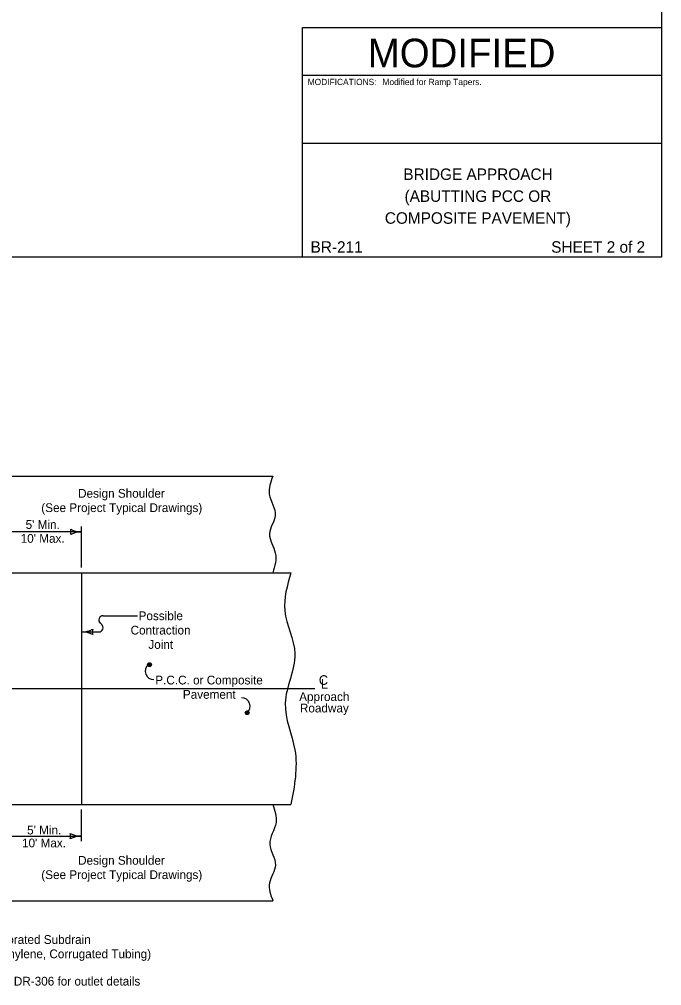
# Model space of a CAD drawing. Extents: x 10045 to 81668, y 6370 to 11018.
# Drawn here: x 22837 to 24068, y 6527 to 8380 of the extents above; entities that cross this region are included whole.
import ezdxf

# ---------------------------------------------------------------- set-up
doc = ezdxf.new("R2010")
doc.units = 0
for name, color, linetype in [('Alignment', 7, 'Continuous'), ('Bridge', 7, 'Continuous'), ('dsnStdLineWork', 7, 'Continuous'), ('Level 5', 7, 'Continuous')]:
    doc.layers.add(name, color=color, linetype=linetype)

msp = doc.modelspace()

# ---------------------------------------------------------------- linework, layer by layer
at = {"layer": 'Alignment'}
for p, q in [((22956.4, 7397.2), (22811.9, 7397.2)), ((22956.4, 7329), (22956.4, 7407.4)), ((22997.7, 7236.4), (23063.3, 7236.4)), ((22993.6, 7220.9), (22992.3, 7222)), ((22956.7, 7205.3), (22989.4, 7205.3)), ((23182, 7096.7), (23182, 7096.7)), ((22955.5, 6865), (22955.5, 6804.1)), ((22811.9, 6813.7), (22955.5, 6813.7))]:
    msp.add_line(p, q, dxfattribs=at)
for centre, radius, start, end in [((22997.7, 7228.2), 8.22, 90, 228.6908), ((22989.4, 7213.6), 8.22, 270, 48.691), ((23094.6, 7130.2), 16.4, 131.3092, 270), ((23262.7, 7062.7), 16.4, 311.309, 90)]:
    msp.add_arc(centre, radius, start, end, dxfattribs=at)
at = {"layer": 'Bridge'}
for p, q in [((23379.5, 8272.7), (24067.5, 8272.7)), ((23379.5, 8142.2), (24067.5, 8142.2))]:
    msp.add_line(p, q, dxfattribs=at)
msp.add_lwpolyline([(23379.5, 8364), (24067.5, 8364), (24067.5, 7924), (23379.5, 7924)], close=True, dxfattribs=at)
at = {"layer": 'dsnStdLineWork'}
for p, q in [((22811.9, 7503.7), (23322.7, 7503.7)), ((22811.9, 7318.7), (23357.5, 7318.7)), ((22956.4, 7318.7), (22956.4, 6874.6)), ((22994.9, 7219.7), (22993.6, 7220.9)), ((21886.8, 7096.7), (23403.1, 7096.7)), ((22811.9, 6874.6), (23357.5, 6874.6)), ((22811.9, 6689.6), (23322.7, 6689.6))]:
    msp.add_line(p, q, dxfattribs=at)
for points in [[(23086.3, 7139.3), (23087.5, 7139.8), (23089.4, 7140.4), (23089.7, 7142.3), (23089.5, 7144), (23088.3, 7145.6), (23086.5, 7145.4), (23084.6, 7145.2), (23083.6, 7143.6), (23083.5, 7142), (23084.6, 7140), (23086, 7139.8), (23087.9, 7140.3), (23089.4, 7141.5), (23089.4, 7143.3), (23088.2, 7144.7), (23086.5, 7144.9), (23084.6, 7144.5), (23084.3, 7143.5), (23083.9, 7142.2), (23084.8, 7140.6), (23086.2, 7140.7), (23087.7, 7140.9), (23088.9, 7141.8), (23088.3, 7143.4), (23087.1, 7144.3), (23085.5, 7144.3), (23085.1, 7143.5), (23084.6, 7142.5), (23085.4, 7141.3), (23086.6, 7141), (23087.6, 7141.5), (23087.7, 7142.7), (23087.1, 7143.5), (23086.1, 7143.8), (23085.6, 7143.4), (23085.3, 7142.7), (23085.8, 7141.8), (23086.6, 7141.6), (23087.3, 7142.1), (23087.2, 7142.7), (23086.6, 7143.1), (23085.9, 7143.1), (23085.9, 7142.5), (23086.5, 7142.2)], [(23273.3, 7047), (23274.5, 7047.6), (23276.4, 7048.2), (23276.8, 7050.1), (23276.5, 7051.8), (23275.3, 7053.3), (23273.5, 7053.2), (23271.6, 7052.9), (23270.7, 7051.4), (23270.5, 7049.8), (23271.7, 7047.7), (23273, 7047.5), (23274.9, 7048), (23276.5, 7049.2), (23276.4, 7051), (23275.2, 7052.5), (23273.5, 7052.6), (23271.6, 7052.3), (23271.3, 7051.2), (23271, 7049.9), (23271.8, 7048.3), (23273.2, 7048.4), (23274.8, 7048.6), (23275.9, 7049.5), (23275.4, 7051.1), (23274.2, 7052), (23272.6, 7052.1), (23272.2, 7051.2), (23271.7, 7050.2), (23272.5, 7049), (23273.6, 7048.7), (23274.7, 7049.3), (23274.8, 7050.4), (23274.2, 7051.3), (23273.1, 7051.6), (23272.6, 7051.1), (23272.3, 7050.5), (23272.9, 7049.5), (23273.6, 7049.4), (23274.3, 7049.8), (23274.2, 7050.4), (23273.7, 7050.8), (23272.9, 7050.8), (23273, 7050.3), (23273.6, 7050)]]:
    msp.add_lwpolyline(points, dxfattribs=at)
for centre in [(23086.5, 7142.6), (23273.6, 7050.3)]:
    msp.add_circle(centre, 3.6, dxfattribs=at)
for centre, radius, start, end in [((22919.2, 7397.2), 17.1, 342.2666, 17.7334), ((22956.4, 7441.5), 44.4, 241.9275, 270), ((22956.4, 7352.8), 44.4, 90, 118.0725), ((22956.6, 7249.7), 44.4, 270, 298.0725), ((22993.9, 7205.3), 17.1, 162.2666, 197.7334), ((22956.6, 7161), 44.4, 61.9275, 90), ((22918.1, 6813.7), 17.2, 342.2666, 17.7334), ((22955.5, 6858.3), 44.6, 241.9275, 270), ((22955.5, 6769.1), 44.6, 90, 118.0725)]:
    msp.add_arc(centre, radius, start, end, dxfattribs=at)
for points in [[(23322.7, 7503.7), (23315.8, 7469.5), (23327.5, 7428.8), (23316.2, 7393.3), (23327.5, 7356.7), (23322.7, 7318.7)], [(23357.5, 7318.7), (23345.6, 7246), (23364.9, 7163.4), (23346.4, 7068.5), (23364.9, 6979), (23357.5, 6874.6)], [(23322.7, 6874.6), (23328.8, 6839.9), (23316.7, 6798.1), (23327.8, 6758.3), (23316.4, 6723.9), (23322.7, 6689.6)]]:
    msp.add_spline(points, degree=3, dxfattribs=at)
at = {"layer": 'Level 5'}
msp.add_lwpolyline([(20932.5, 9944), (24067.5, 9944), (24067.5, 7924), (20932.5, 7924)], close=True, dxfattribs=at)

# ---------------------------------------------------------------- texts
at = {"layer": 'Alignment'}
for s, height, p in [('Design Shoulder', 16.8, (22949.7, 7462.6)), ('(See Project Typical Drawings)', 16.8, (22879.2, 7435.1)), ("5' Min.", 16.8, (22849.2, 7402.8)), ("10' Max.", 16.8, (22839.7, 7376.2)), ('Possible', 16.8, (23065.6, 7227.8)), ('Contraction', 16.8, (23050.3, 7200.3)), ('Joint', 16.8, (23084.3, 7172.8)), ('P.C.C. or Composite', 16.8, (23097.5, 7104.6)), ('C', 18.4, (23410.8, 7103.8)), ('L', 18.4, (23414.6, 7096.6)), ('Pavement', 16.8, (23150.4, 7077.1)), ('Approach', 16.8, (23373.2, 7072.8)), ('Roadway', 16.8, (23374.6, 7050.9)), ("5' Min.", 16.8, (22852, 6817)), ("10' Max.", 16.8, (22842.3, 6792.2)), ('Design Shoulder', 16.8, (22949.7, 6758.9)), ('(See Project Typical Drawings)', 16.8, (22879.2, 6731.4)), ('4" Perforated Subdrain ', 16.8, (22746.1, 6607.1)), ('(Polyethylene, Corrugated Tubing)', 16.8, (22746.1, 6579.6)), ('See DR-306 for outlet details', 16.8, (22780.4, 6527.2))]:
    msp.add_text(s, height=height, dxfattribs=at).set_placement(p)
at = {"layer": 'Bridge'}
for s, height, p in [('MODIFIED', 55, (23504.6, 8287.8)), ('MODIFICATIONS:', 12, (23389.5, 8253.8)), ('Modified for Ramp Tapers.', 12, (23532.7, 8253.8)), ('BRIDGE APPROACH', 22, (23572.7, 8071.9)), ('(ABUTTING PCC OR', 22, (23575, 8029.9)), ('COMPOSITE PAVEMENT)', 22, (23537.3, 7987.9)), ('BR-211', 22, (23395, 7932.4)), ('SHEET 2 of 2', 22, (23856, 7932.4))]:
    msp.add_text(s, height=height, dxfattribs=at).set_placement(p)

doc.saveas('drawing.dxf')
